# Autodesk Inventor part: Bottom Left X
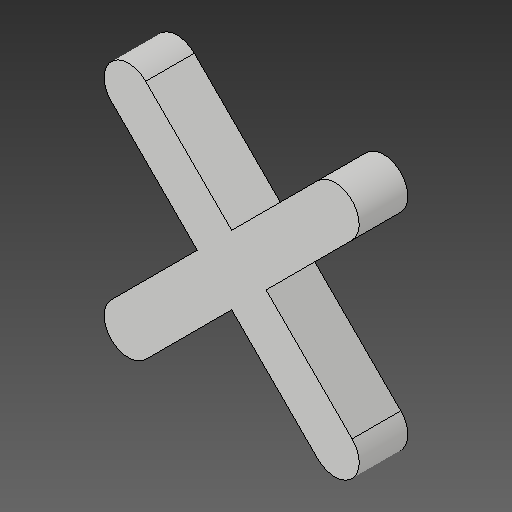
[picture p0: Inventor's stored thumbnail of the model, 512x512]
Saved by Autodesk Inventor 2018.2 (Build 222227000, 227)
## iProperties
Created: 2018-03
Part Number: Bottom Left X
Material: Generic
Document SubType Name: Modeling
Designer: PeterMaxwell-Stewart
Mass: 1.57135 g
Surface Area: 12.8562 cm^2
Volume: 1.57135 cm^3
Density: 1 g/cm^3
Appearance: Default
Author: PeterMaxwell-Stewart
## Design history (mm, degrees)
derived "O's and X's.ipt"
feature "Bottom Left X::O's and X's.ipt" dims "d0" = 10
tag "TaggingFeature1"
body "Solid1"
